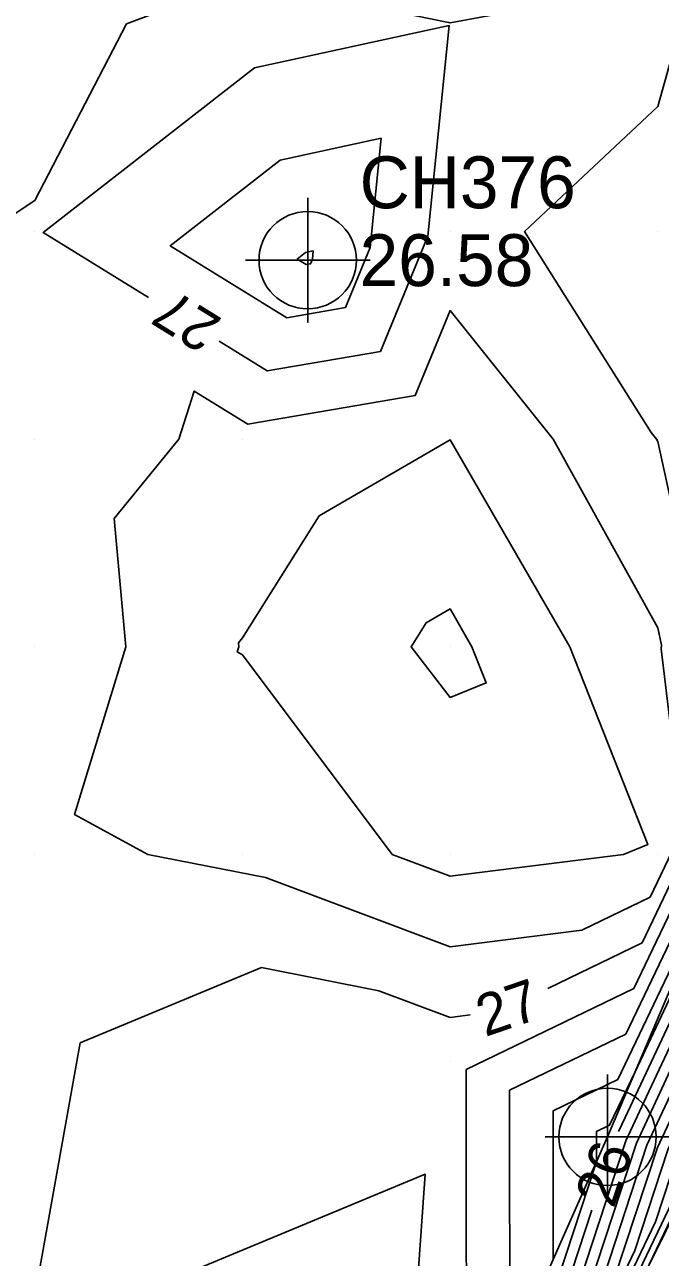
# Model space of a CAD drawing. Extents: x 2531902 to 2533249, y 715219 to 716099.
# Drawn here: x 2532689.5 to 2532720.1, y 715360.6 to 715420 of the extents above; entities that cross this region are included whole.
import ezdxf

# ---------------------------------------------------------------- set-up
doc = ezdxf.new("R2010")
doc.units = 0
for name, color, linetype in [('DTM Contours Major', 7, 'Continuous'), ('DTM Contours Major Text', 7, 'Continuous'), ('DTM Contours Minor', 7, 'Continuous'), ('Exist DTM Breakline', 7, 'Continuous'), ('Exist DTM Breakline Cogo Point CELL', 7, 'Continuous'), ('Exist DTM QL2 LIDAR Elevation Point', 7, 'Continuous'), ('Exist DTM Regular Point CELL', 7, 'Continuous'), ('Exist DTM Regular Point Cogo Elevation', 7, 'Continuous'), ('Exist DTM Regular Point Cogo Number', 7, 'Continuous')]:
    doc.layers.add(name, color=color, linetype=linetype)

msp = doc.modelspace()

# ---------------------------------------------------------------- linework, layer by layer
at = {"layer": 'DTM Contours Major'}
for points in [[(2532741.786, 715454.712), (2532740, 715454.12), (2532735.815, 715454.185), (2532735.815, 715450), (2532736.766, 715443.234), (2532734.728, 715440), (2532740, 715431.343), (2532740.309, 715430.303), (2532738.444, 715415.679), (2532737.727, 715413.532), (2532737.089, 715411.85), (2532736.399, 715409.901), (2532736.295, 715409.657), (2532732.71, 715399.177), (2532731.502, 715396.369), (2532726.475, 715384.443), (2532718.431, 715367.324), (2532718.116, 715366.65)], [(2532752.255, 715446.836), (2532751.43, 715443.503), (2532750.533, 715440.609), (2532749.886, 715438.88), (2532745.152, 715424.715), (2532739.574, 715410.002), (2532739.262, 715409.121), (2532738.641, 715407.674), (2532737.024, 715402.95), (2532729.895, 715386.376), (2532727.683, 715381.128), (2532724.143, 715373.594), (2532720.491, 715365.772), (2532718.9, 715360.92), (2532715.573, 715353.957)], [(2532685.866, 715408.146), (2532687.738, 715410), (2532690, 715411.491), (2532694.423, 715420), (2532700, 715422.116), (2532709.929, 715420.071), (2532710, 715420.053), (2532718.389, 715421.611), (2532720, 715421.687), (2532722.31, 715420), (2532720.873, 715419.127), (2532720, 715416.024), (2532713.584, 715410), (2532719.681, 715400.319), (2532719.937, 715400), (2532720, 715399.886), (2532721.982, 715390.851), (2532721.73, 715388.827), (2532722.492, 715382.528), (2532719.242, 715375.74), (2532714.707, 715373.543)], [(2532709.958, 715419.931), (2532700.584, 715417.887), (2532690.404, 715409.958), (2532695.478, 715406.821)], [(2532698.88, 715404.718), (2532701.198, 715403.285), (2532706.644, 715404.22), (2532708.926, 715409.784), (2532709.958, 715419.931)], [(2532710.969, 715372.264), (2532710, 715372.142), (2532706.569, 715373.431), (2532700.912, 715374.544), (2532692.194, 715370.918), (2532684.184, 715326.25), (2532682.433, 715320.576), (2532692.516, 715313.468), (2532688.854, 715304.389)], [(2532716.828, 715362.865), (2532713.94, 715354.053), (2532709.077, 715343.878), (2532703.063, 715333.339), (2532702.841, 715332.857), (2532699.588, 715325.415), (2532696.744, 715319.245), (2532691.501, 715306.246)]]:
    msp.add_lwpolyline(points, dxfattribs=at)
at = {"layer": 'DTM Contours Minor'}
for points in [[(2532749.608, 715431.425), (2532741.064, 715408.893), (2532740.98, 715408.654), (2532740.048, 715406.484), (2532739.613, 715405.213), (2532728.931, 715380.381), (2532728.407, 715379.139), (2532727.57, 715377.356), (2532722.011, 715365.449), (2532721.876, 715365.04), (2532719.41, 715359.879), (2532716.556, 715348.815), (2532715.589, 715346.812), (2532715.359, 715346.327), (2532704.747, 715322.677), (2532704.166, 715321.46), (2532696.617, 715308.576)], [(2532748.123, 715429.188), (2532740.568, 715409.263), (2532740.407, 715408.809), (2532739.579, 715406.881), (2532738.75, 715404.458), (2532729.252, 715382.379), (2532728.166, 715379.802), (2532726.427, 715376.102), (2532721.504, 715365.556), (2532720.884, 715363.666), (2532709.495, 715339.833), (2532709.32, 715339.158), (2532709.261, 715339.035), (2532708.13, 715336.651), (2532707.619, 715335.511), (2532703.945, 715327.826), (2532695.291, 715309.055), (2532695.206, 715308.845)], [(2532737.431, 715427.431), (2532735.921, 715413.08), (2532730, 715412.388), (2532728.515, 715411.485), (2532728.096, 715410), (2532728.368, 715408.368), (2532731.784, 715398.699), (2532735.747, 715410.057), (2532735.847, 715410.114), (2532735.827, 715410.056), (2532735.826, 715410.054), (2532731.847, 715398.423), (2532731.824, 715398.368), (2532726.234, 715385.106), (2532718.912, 715369.524), (2532717.68, 715366.95), (2532717.047, 715366.644), (2532717.048, 715365.188), (2532712.947, 715352.68)], [(2532743.639, 715426.808), (2532740.697, 715418.005), (2532738.083, 715411.111), (2532737.544, 715409.589), (2532737.233, 715408.864), (2532734.436, 715400.686), (2532730.859, 715392.372), (2532726.958, 715383.117), (2532720.716, 715369.832), (2532718.971, 715366.095), (2532715.924, 715356.8), (2532709.011, 715342.336), (2532704.732, 715334.836), (2532704.258, 715333.808), (2532701.941, 715328.507), (2532696.328, 715316.334), (2532692.559, 715306.988)], [(2532746.638, 715426.951), (2532740.071, 715409.632), (2532739.835, 715408.965), (2532739.11, 715407.278), (2532737.887, 715403.704), (2532729.574, 715384.378), (2532727.924, 715380.465), (2532725.285, 715374.848), (2532720.997, 715365.664), (2532719.892, 715362.293), (2532708.881, 715339.251), (2532708.07, 715337.83), (2532707.092, 715335.71), (2532706.647, 715334.693), (2532695.498, 715310.511), (2532694.677, 715308.474)], [(2532734.432, 715424.432), (2532733.531, 715415.873), (2532730, 715415.46), (2532726.604, 715413.396), (2532725.648, 715410), (2532726.269, 715406.269), (2532728.908, 715398.801), (2532726.958, 715395.097), (2532727.381, 715393.169), (2532726.778, 715388.322), (2532727.435, 715389.192), (2532725.992, 715385.77), (2532724.134, 715381.816), (2532718.07, 715369.148), (2532714.956, 715367.639), (2532714.961, 715360.475)], [(2532743.667, 715422.478), (2532739.077, 715410.372), (2532738.69, 715409.277), (2532738.171, 715408.071), (2532736.162, 715402.195), (2532730.217, 715388.375), (2532727.441, 715381.791), (2532723, 715372.34), (2532719.984, 715365.879), (2532717.908, 715359.546), (2532708.946, 715340.793), (2532706.401, 715336.333), (2532705.675, 715334.759), (2532704.294, 715331.6), (2532695.913, 715313.423), (2532693.618, 715307.731)], [(2532731.434, 715421.434), (2532731.142, 715418.665), (2532730, 715418.532), (2532724.694, 715415.306), (2532723.2, 715410), (2532724.171, 715404.171), (2532725.926, 715399.203), (2532724.629, 715396.738), (2532725.581, 715392.396), (2532724.873, 715386.698), (2532725.062, 715385.135), (2532718.461, 715371.345), (2532712.866, 715368.635), (2532712.874, 715355.762), (2532710.963, 715349.933), (2532709.175, 715346.191), (2532704.757, 715338.45), (2532705.576, 715350.018), (2532698.003, 715346.868), (2532694.945, 715329.816), (2532692.441, 715321.704), (2532695.676, 715319.423), (2532689.912, 715305.131)], [(2532741.041, 715421.243), (2532739.212, 715415.768), (2532737.586, 715411.481), (2532736.972, 715409.745), (2532736.764, 715409.261), (2532733.573, 715399.932), (2532731.181, 715394.371), (2532726.717, 715383.78), (2532719.573, 715368.578), (2532718.464, 715366.202), (2532714.932, 715355.427), (2532709.044, 715343.107), (2532703.897, 715334.088), (2532703.549, 715333.333), (2532700.764, 715326.961), (2532696.536, 715317.79), (2532692.03, 715306.617)], [(2532727.363, 715420), (2532722.783, 715417.217), (2532720.753, 715410), (2532722.072, 715402.072), (2532722.944, 715399.604), (2532722.3, 715398.379), (2532723.781, 715391.624), (2532723.302, 715387.763), (2532723.777, 715383.831), (2532718.852, 715373.542), (2532710.776, 715369.631), (2532710.787, 715351.048), (2532709.971, 715348.56), (2532709.208, 715346.962), (2532707.322, 715343.657), (2532708.803, 715364.593), (2532695.098, 715358.893), (2532689.565, 715328.033), (2532687.437, 715321.14), (2532694.096, 715316.446), (2532689.383, 715304.76)], [(2532742.182, 715420.242), (2532738.58, 715410.741), (2532738.117, 715409.433), (2532737.702, 715408.467), (2532735.299, 715401.441), (2532730.538, 715390.374), (2532727.2, 715382.454), (2532721.858, 715371.086), (2532719.477, 715365.987), (2532716.916, 715358.173), (2532708.979, 715341.564), (2532705.566, 715335.585), (2532704.966, 715334.283), (2532703.118, 715330.054), (2532696.121, 715314.878), (2532693.089, 715307.36)], [(2532706.685, 715414.497), (2532701.814, 715413.435), (2532696.525, 715409.316), (2532702.133, 715405.849), (2532704.963, 715406.335), (2532706.148, 715409.225), (2532706.685, 715414.497)], [(2532703.411, 715409.064), (2532703.044, 715408.984), (2532702.645, 715408.674), (2532703.068, 715408.412), (2532703.281, 715408.449), (2532703.371, 715408.667), (2532703.411, 715409.064)], [(2532719.633, 715377.937), (2532716.344, 715376.344), (2532710, 715375.547), (2532701.114, 715378.886), (2532695.45, 715380), (2532691.917, 715381.917), (2532694.38, 715390), (2532693.825, 715396.175), (2532696.944, 715400), (2532697.685, 715402.315), (2532700.263, 715400.721), (2532708.325, 715402.106), (2532710, 715406.19), (2532714.958, 715400), (2532720, 715390.908), (2532720.182, 715390.078), (2532720.159, 715389.892), (2532721.207, 715381.224), (2532719.633, 715377.937)], [(2532710, 715378.953), (2532707.213, 715380), (2532700, 715389.612), (2532699.749, 715389.749), (2532699.825, 715390), (2532699.808, 715390.192), (2532700, 715390.427), (2532703.699, 715396.301), (2532710, 715399.968), (2532715.766, 715390), (2532719.525, 715380.475), (2532718.343, 715380), (2532710, 715378.953)], [(2532711.055, 715390), (2532710, 715391.824), (2532708.847, 715391.153), (2532708.12, 715390), (2532710, 715387.556), (2532711.743, 715388.257), (2532711.055, 715390)]]:
    msp.add_lwpolyline(points, dxfattribs=at)
at = {"layer": 'Exist DTM Breakline'}
for points in [[(2532762.131, 715466.43), (2532735.821, 715410.058), (2532731.83, 715398.408), (2532725.91, 715385.995), (2532717.58, 715366.39), (2532709.232, 715347.537), (2532701.59, 715332.018), (2532697.17, 715322.237)], [(2532695.267, 715308.888), (2532708.85, 715338.53), (2532728.632, 715378.522), (2532741.621, 715408.479), (2532758.675, 715450.751), (2532764.932, 715465.184)]]:
    msp.add_lwpolyline(points, dxfattribs=at)
at = {"layer": 'Exist DTM Breakline Cogo Point CELL'}
msp.add_lwpolyline([(2532717.58, 715369.39), (2532717.58, 715363.39), (2532717.58, 715366.39), (2532720.58, 715366.39), (2532714.58, 715366.39)], dxfattribs=at)
msp.add_circle((2532717.58, 715366.39), 2.344, dxfattribs=at)
at = {"layer": 'Exist DTM QL2 LIDAR Elevation Point'}
for p, q in [((2532690, 715410), (2532690, 715410)), ((2532710, 715410), (2532710, 715410)), ((2532720, 715410), (2532720, 715410)), ((2532690, 715400), (2532690, 715400)), ((2532700, 715400), (2532700, 715400)), ((2532710, 715400), (2532710, 715400)), ((2532720, 715400), (2532720, 715400)), ((2532690, 715390), (2532690, 715390)), ((2532700, 715390), (2532700, 715390)), ((2532710, 715390), (2532710, 715390)), ((2532720, 715390), (2532720, 715390)), ((2532690, 715380), (2532690, 715380)), ((2532700, 715380), (2532700, 715380)), ((2532710, 715380), (2532710, 715380)), ((2532720, 715380), (2532720, 715380)), ((2532710, 715370), (2532710, 715370))]:
    msp.add_line(p, q, dxfattribs=at)
at = {"layer": 'Exist DTM Regular Point CELL'}
msp.add_lwpolyline([(2532703.144, 715411.621), (2532703.144, 715405.621), (2532703.144, 715408.621), (2532706.144, 715408.621), (2532700.144, 715408.621)], dxfattribs=at)
msp.add_circle((2532703.144, 715408.621), 2.344, dxfattribs=at)

# ---------------------------------------------------------------- texts
at = {"layer": 'DTM Contours Major Text'}
for s, rotation, p in [('27', 148.27731, (2532699.091, 715405.763)), ('27', 18.89234, (2532711.689, 715371.197)), ('26', 71.20638, (2532717.873, 715362.901))]:
    msp.add_text(s, height=2, rotation=rotation, dxfattribs=at).set_placement(p)
at = {"layer": 'Exist DTM Regular Point Cogo Elevation'}
msp.add_text('26.58', height=2.5, dxfattribs=at).set_placement((2532705.644, 715407.371))
at = {"layer": 'Exist DTM Regular Point Cogo Number'}
msp.add_text('CH376', height=2.5, dxfattribs=at).set_placement((2532705.644, 715411.121))

doc.saveas('drawing.dxf')
